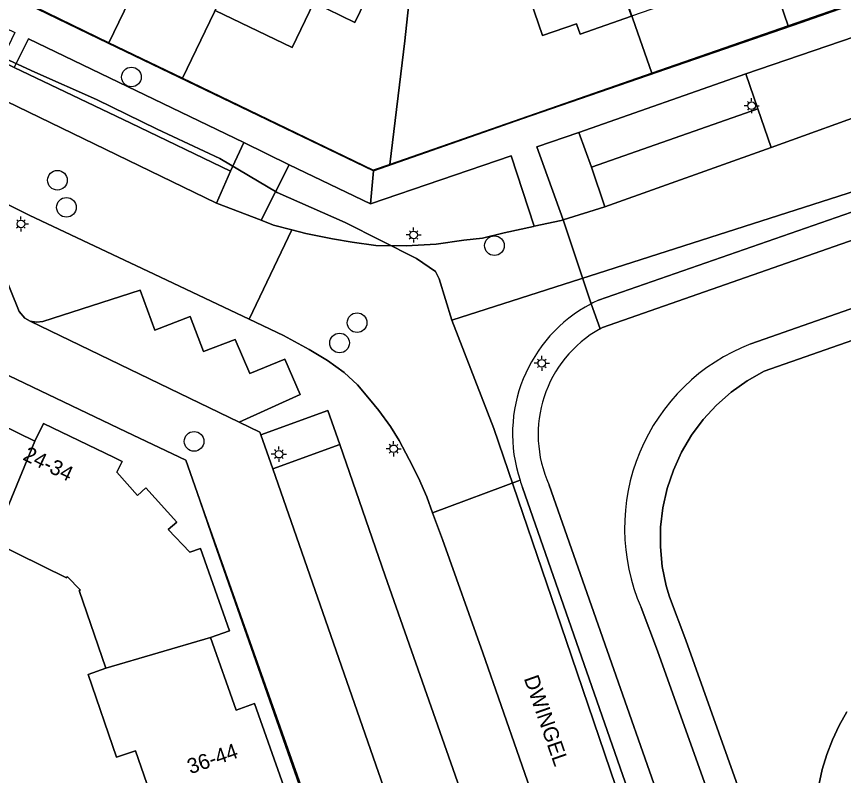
# Model space of a CAD drawing. Extents: x 124901 to 125496, y 515369 to 515789.
# Drawn here: x 125323.3 to 125378, y 515560.1 to 515610.2 of the extents above; entities that cross this region are included whole.
import ezdxf

# ---------------------------------------------------------------- set-up
doc = ezdxf.new("R2010")
doc.units = 0
for name, color, linetype in [('Berm', 7, 'Continuous'), ('Gebouw', 7, 'Continuous'), ('Inrit', 7, 'Continuous'), ('Lichtmast', 7, 'Continuous'), ('Onbegroeid terrein', 7, 'Continuous'), ('Parkeren', 7, 'Continuous'), ('Perceelsgrenzen', 7, 'Continuous'), ('Putten', 7, 'Continuous'), ('Scheiding', 7, 'Continuous'), ('Teksten', 7, 'Continuous'), ('Vegetatie', 7, 'Continuous'), ('Voetpad', 7, 'Continuous'), ('Water', 7, 'Continuous'), ('Wegen drempel verkeerseiland', 7, 'Continuous'), ('Wegen lokale weg', 7, 'Continuous')]:
    doc.layers.add(name, color=color, linetype=linetype)

msp = doc.modelspace()

# ---------------------------------------------------------------- linework, layer by layer
at = {"layer": 'Berm'}
for points in [[(125410.926, 515602.835), (125410.786, 515604.876), (125410.291, 515606.52), (125362.019, 515589.66), (125361.874, 515589.581)], [(125371.825, 515588.577), (125407.43, 515601.037), (125410.404, 515597.859), (125410.926, 515602.835)], [(125358.506, 515579.257), (125369.841, 515546.911)], [(125370.167, 515525.912), (125361.577, 515507.943), (125364.809, 515506.424), (125365.599, 515506.052), (125368.756, 515512.727), (125374.572, 515524.721), (125376.357, 515528.013), (125376.824, 515529.274), (125377.068, 515530.536), (125377.185, 515532.051), (125377.232, 515533.336), (125377.157, 515534.454), (125377.004, 515535.615), (125376.571, 515537.55), (125374.806, 515542.701), (125371.741, 515551.276), (125365.658, 515568.312), (125364.58, 515571.173)]]:
    msp.add_lwpolyline(points, dxfattribs=at)
for centre, radius, start, end in [((125365.776, 515582.597), 8, 119.1891, 204.6751), ((125376.535, 515576.406), 13.05, 111.1555, 203.6422)]:
    msp.add_arc(centre, radius, start, end, dxfattribs=at)
at = {"layer": 'Gebouw'}
for points in [[(125341.51, 515608.16), (125342.95, 515611.13), (125345.67, 515609.82), (125348.53, 515615.73), (125345.576, 515617.156), (125345.15, 515616.273), (125343.214, 515617.208), (125344.956, 515620.809), (125344.931, 515620.821), (125342.181, 515622.149), (125342.036, 515622.219), (125336.431, 515610.613)], [(125351.455, 515619.162), (125353.465, 515613.432), (125356.192, 515614.378), (125356.733, 515612.819), (125358.075, 515608.952), (125360.315, 515609.732), (125360.555, 515609.042), (125363.95, 515610.227), (125360.703, 515619.532), (125357.783, 515618.514), (125356.895, 515621.064)], [(125316.47, 515578.03), (125315.95, 515576.86), (125321.2, 515574.34), (125321.76, 515575.5), (125324.52, 515582.16), (125319.95, 515584.37), (125320.51, 515585.54), (125315.398, 515588.013), (125315.28, 515588.07), (125311.57, 515580.39)], [(125333.89, 515576.81), (125331.84, 515579.07), (125331.29, 515578.56), (125329.93, 515580.1), (125330.28, 515580.82), (125329.75, 515581.076), (125325.08, 515583.33), (125324.52, 515582.16), (125321.76, 515575.5), (125326.6, 515573.13), (125326.65, 515573.22), (125327.54, 515572.32), (125327.44, 515572.29), (125329.21, 515567.16), (125336.13, 515569.19), (125337.37, 515569.62), (125335.46, 515575.07), (125334.75, 515574.83), (125333.33, 515576.31)], [(125331.6, 515556.44), (125333.5, 515550.97), (125334.74, 515551.4), (125341.4, 515554.1), (125339.73, 515558.89), (125340.96, 515559.33), (125339.04, 515564.82), (125337.81, 515564.39), (125336.13, 515569.19), (125329.21, 515567.16), (125328.03, 515566.73), (125329.91, 515561.27), (125331.16, 515561.69), (125332.84, 515556.88)]]:
    msp.add_lwpolyline(points, close=True, dxfattribs=at)
at = {"layer": 'Inrit'}
for points in [[(125378.669, 515608.861), (125371.508, 515606.42), (125372.3, 515604.105), (125373.169, 515601.564), (125380.382, 515604.143), (125379.481, 515606.624)], [(125362.177, 515597.633), (125361.312, 515600.252), (125360.459, 515602.535), (125357.695, 515601.597), (125359.425, 515596.766)], [(125339.465, 515596.749), (125341.317, 515600.419), (125338.322, 515601.888), (125337.438, 515599.997), (125336.519, 515597.882)]]:
    msp.add_lwpolyline(points, close=True, dxfattribs=at)
at = {"layer": 'Lichtmast'}
for p, q in [((125371.674, 515604.525), (125371.604, 515604.596)), ((125371.886, 515604.613), (125371.886, 515604.813)), ((125372.098, 515604.525), (125372.169, 515604.597)), ((125371.586, 515604.314), (125371.386, 515604.313)), ((125371.674, 515604.101), (125371.602, 515604.03)), ((125371.886, 515604.013), (125371.886, 515603.813)), ((125372.098, 515604.101), (125372.168, 515604.03)), ((125372.186, 515604.313), (125372.386, 515604.313)), ((125323.596, 515596.801), (125323.596, 515597.001)), ((125323.384, 515596.713), (125323.314, 515596.784)), ((125323.808, 515596.713), (125323.879, 515596.785)), ((125323.896, 515596.501), (125324.096, 515596.501)), ((125323.384, 515596.289), (125323.312, 515596.218)), ((125323.596, 515596.201), (125323.596, 515596.001)), ((125323.808, 515596.289), (125323.878, 515596.218)), ((125349.247, 515595.775), (125349.047, 515595.774)), ((125349.335, 515595.986), (125349.265, 515596.057)), ((125349.547, 515596.074), (125349.547, 515596.274)), ((125349.759, 515595.986), (125349.83, 515596.058)), ((125349.847, 515595.774), (125350.047, 515595.774)), ((125349.335, 515595.562), (125349.263, 515595.491)), ((125349.547, 515595.474), (125349.547, 515595.274)), ((125349.759, 515595.562), (125349.829, 515595.491)), ((125357.805, 515587.509), (125357.735, 515587.58)), ((125358.017, 515587.597), (125358.017, 515587.797)), ((125358.229, 515587.509), (125358.3, 515587.581)), ((125357.717, 515587.298), (125357.517, 515587.297)), ((125357.805, 515587.085), (125357.733, 515587.014)), ((125358.229, 515587.085), (125358.299, 515587.014)), ((125358.317, 515587.297), (125358.517, 515587.297)), ((125358.017, 515586.997), (125358.017, 515586.797)), ((125348.223, 515581.95), (125348.223, 515582.15)), ((125340.431, 515581.505), (125340.361, 515581.576)), ((125340.643, 515581.593), (125340.643, 515581.793)), ((125340.855, 515581.505), (125340.926, 515581.577)), ((125347.923, 515581.651), (125347.723, 515581.65)), ((125348.011, 515581.862), (125347.941, 515581.933)), ((125348.435, 515581.862), (125348.506, 515581.934)), ((125348.523, 515581.65), (125348.723, 515581.65)), ((125340.343, 515581.294), (125340.143, 515581.293)), ((125340.431, 515581.081), (125340.359, 515581.01)), ((125340.855, 515581.081), (125340.925, 515581.01)), ((125340.943, 515581.293), (125341.143, 515581.293)), ((125348.011, 515581.438), (125347.939, 515581.367)), ((125348.223, 515581.35), (125348.223, 515581.15)), ((125348.435, 515581.438), (125348.505, 515581.367)), ((125340.643, 515580.993), (125340.643, 515580.793))]:
    msp.add_line(p, q, dxfattribs=at)
for centre in [(125371.886, 515604.313), (125323.596, 515596.501), (125349.547, 515595.774), (125358.017, 515587.297), (125348.223, 515581.65), (125340.643, 515581.293)]:
    msp.add_circle(centre, 0.25, dxfattribs=at)
at = {"layer": 'Onbegroeid terrein'}
msp.add_lwpolyline([(125353.465, 515613.432), (125351.455, 515619.162), (125356.895, 515621.064), (125357.783, 515618.514), (125360.703, 515619.532), (125360.14, 515621.146), (125362.915, 515622.113), (125362.59, 515623.046), (125368.161, 515624.989), (125370.174, 515619.255), (125367.444, 515618.296), (125367.991, 515616.739), (125369.345, 515612.882), (125367.109, 515612.102), (125367.349, 515611.413), (125363.95, 515610.227), (125360.555, 515609.042), (125360.315, 515609.732), (125358.075, 515608.952), (125356.733, 515612.819), (125356.192, 515614.378)], close=True, dxfattribs=at)
for points in [[(125306.97, 515619.275), (125328.714, 515608.752), (125346.892, 515600.023), (125356.759, 515603.471), (125375.169, 515609.812), (125392.301, 515615.845)], [(125348.53, 515615.73), (125345.67, 515609.82), (125342.95, 515611.13), (125341.51, 515608.16), (125336.431, 515610.613)], [(125342.972, 515556.928), (125335.865, 515576.993), (125334.482, 515580.899), (125330.544, 515582.774), (125318.137, 515588.683)], [(125319.95, 515584.37), (125324.52, 515582.16), (125325.08, 515583.33), (125329.75, 515581.076), (125330.28, 515580.82), (125329.93, 515580.1), (125331.29, 515578.56), (125331.84, 515579.07), (125333.89, 515576.81), (125333.33, 515576.31), (125334.75, 515574.83), (125335.46, 515575.07), (125337.37, 515569.62), (125336.13, 515569.19), (125337.81, 515564.39), (125339.04, 515564.82), (125340.96, 515559.33)], [(125332.84, 515556.88), (125331.16, 515561.69), (125329.91, 515561.27), (125328.03, 515566.73), (125329.21, 515567.16), (125327.44, 515572.29), (125327.54, 515572.32), (125326.65, 515573.22), (125326.6, 515573.13), (125321.76, 515575.5)]]:
    msp.add_lwpolyline(points, dxfattribs=at)
at = {"layer": 'Parkeren'}
for points in [[(125336.519, 515597.882), (125337.438, 515599.997), (125330.856, 515603.155), (125323.154, 515606.845), (125322.28, 515607.264), (125317.991, 515609.319), (125316.985, 515609.801), (125315.999, 515607.807)], [(125361.312, 515600.252), (125362.177, 515597.633), (125373.169, 515601.564), (125372.3, 515604.105)], [(125338.012, 515583.417), (125342.054, 515585.227), (125341.043, 515587.567), (125338.714, 515586.619), (125337.747, 515588.874), (125335.651, 515588.079), (125334.772, 515590.382), (125332.44, 515589.485), (125331.466, 515592.126), (125325.041, 515590.061), (125324.618, 515590.025), (125324.203, 515590.081)], [(125348.263, 515557.283), (125352.745, 515558.815), (125352.736, 515558.839), (125347.675, 515573.262), (125344.68, 515581.93), (125340.233, 515580.319)]]:
    msp.add_lwpolyline(points, close=True, dxfattribs=at)
at = {"layer": 'Perceelsgrenzen'}
for points in [[(125374.301, 515609.602), (125365.21, 515636.12), (125368.75, 515637.34), (125374.35, 515639.28), (125378.923, 515625.863), (125383.515, 515612.815)], [(125365.292, 515606.46), (125360.724, 515619.519), (125356.08, 515632.98), (125365.21, 515636.12), (125374.301, 515609.602)], [(125329.408, 515608.477), (125324.548, 515610.824), (125330.57, 515623.313), (125336.513, 515635.621), (125336.653, 515635.553), (125341.375, 515633.273), (125335.859, 515621.848), (125335.643, 515621.952), (125335.217, 515621.069), (125335.433, 515620.965)], [(125334.269, 515606.129), (125329.408, 515608.477), (125335.433, 515620.965), (125335.217, 515621.069), (125335.643, 515621.952), (125335.859, 515621.848), (125341.375, 515633.273), (125346.08, 515631), (125346.238, 515630.925), (125340.722, 515619.499), (125340.938, 515619.395), (125340.512, 515618.512), (125340.296, 515618.617)], [(125347.97, 515600.42), (125348.96, 515608.6), (125351.11, 515628.61), (125352.36, 515631.64), (125356.08, 515632.98), (125360.724, 515619.519), (125365.292, 515606.46)], [(125334.269, 515606.129), (125340.296, 515618.617), (125340.512, 515618.512), (125340.938, 515619.395), (125340.722, 515619.499), (125346.238, 515630.925), (125351.11, 515628.61), (125348.96, 515608.6), (125347.97, 515600.42), (125346.87, 515600.05)]]:
    msp.add_lwpolyline(points, close=True, dxfattribs=at)
for points in [[(125316.445, 515610.498), (125321.38, 515607.963), (125324.515, 515606.531), (125328.594, 515604.73), (125332.608, 515602.764), (125336.73, 515600.825), (125340.526, 515598.575), (125345.025, 515596.601), (125349.739, 515594.219), (125350.982, 515593.372), (125351.229, 515592.881), (125352.068, 515590.151), (125423.088, 515612.915)], [(125383.515, 515612.815), (125374.301, 515609.602), (125365.292, 515606.46), (125347.97, 515600.42), (125346.87, 515600.05), (125334.269, 515606.129), (125329.408, 515608.477), (125324.548, 515610.824)], [(125423.088, 515612.915), (125352.068, 515590.151), (125354.844, 515582.98), (125359.632, 515568.992), (125367.282, 515546.531), (125373.39, 515529.447), (125374.833, 515525.657), (125370.2, 515515.457), (125361.451, 515496.989), (125354.147, 515481.936), (125345.37, 515463.116), (125339.28, 515450.017), (125332.914, 515437.391), (125330.261, 515431.98), (125328.194, 515427.596), (125330.281, 515426.402), (125332.521, 515425.055), (125348.134, 515457.345), (125358.716, 515479.229), (125369.827, 515502.206), (125375.06, 515499.729), (125385.193, 515494.823)], [(125339.28, 515450.017), (125345.37, 515463.116), (125354.147, 515481.936), (125361.451, 515496.989), (125370.2, 515515.457), (125374.833, 515525.657), (125373.39, 515529.447), (125367.282, 515546.531), (125359.632, 515568.992), (125354.844, 515582.98), (125352.068, 515590.151), (125351.229, 515592.881), (125350.982, 515593.372), (125349.739, 515594.219), (125345.025, 515596.601), (125340.526, 515598.575), (125336.73, 515600.825), (125332.608, 515602.764), (125328.594, 515604.73), (125324.515, 515606.531), (125321.38, 515607.963), (125316.445, 515610.498)], [(125271.62, 515558.71), (125280.85, 515577.9), (125284.46, 515579.06), (125285.19, 515580.58), (125290.142, 515590.841), (125293.8, 515598.46), (125295.97, 515602.96), (125301.013, 515600.518), (125305.831, 515598.186), (125316.893, 515592.83), (125318.137, 515588.683), (125334.482, 515580.899), (125336.39, 515575.4), (125352.406, 515529.691)], [(125271.62, 515558.71), (125280.85, 515577.9), (125284.46, 515579.06), (125285.19, 515580.58), (125290.175, 515578.191), (125292.62, 515577.02), (125295.08, 515575.85), (125296.14, 515578.13), (125299.998, 515586.108), (125305.831, 515598.186), (125316.893, 515592.83), (125318.137, 515588.683), (125334.482, 515580.899), (125336.39, 515575.4), (125352.406, 515529.691)], [(125378.185, 515564.28), (125377.676, 515563.369), (125377.233, 515562.425), (125376.859, 515561.451), (125376.554, 515560.454), (125376.322, 515559.437), (125376.162, 515558.406), (125376.077, 515557.386), (125376.061, 515556.363), (125376.114, 515555.341), (125376.237, 515554.325), (125376.428, 515553.32), (125376.687, 515552.33), (125377.013, 515551.36), (125377.404, 515550.414), (125377.858, 515549.497), (125378.373, 515548.613)], [(125378.373, 515548.613), (125377.858, 515549.497), (125377.404, 515550.414), (125377.013, 515551.36), (125376.687, 515552.33), (125376.428, 515553.32), (125376.237, 515554.325), (125376.114, 515555.341), (125376.061, 515556.363), (125376.077, 515557.386), (125376.162, 515558.406), (125376.322, 515559.437), (125376.554, 515560.454), (125376.859, 515561.451), (125377.233, 515562.425), (125377.676, 515563.369), (125378.185, 515564.28)]]:
    msp.add_lwpolyline(points, dxfattribs=at)
at = {"layer": 'Putten'}
for centre in [(125330.9, 515606.21), (125326.01, 515599.39), (125326.6, 515597.6), (125354.89, 515595.07), (125345.81, 515589.98), (125344.65, 515588.64), (125335.04, 515582.14)]:
    msp.add_circle(centre, 0.65, dxfattribs=at)
at = {"layer": 'Scheiding'}
for points in [[(125406.86, 515598.719), (125372.716, 515586.786)], [(125372.716, 515586.786), (125371.587, 515586.149), (125370.531, 515585.397), (125369.559, 515584.539), (125368.683, 515583.584), (125367.911, 515582.542), (125367.252, 515581.426), (125366.713, 515580.246), (125366.301, 515579.017), (125366.019, 515577.752), (125365.871, 515576.464), (125365.859, 515575.168), (125365.982, 515573.877), (125366.239, 515572.607), (125366.451, 515571.879)], [(125367.41, 515505.2), (125370.56, 515511.863), (125376.33, 515523.768), (125378.183, 515527.185), (125378.756, 515528.733), (125379.053, 515530.268), (125379.182, 515531.938), (125379.234, 515533.366), (125379.148, 515534.652), (125378.975, 515535.965), (125378.499, 515538.094), (125376.694, 515543.362), (125373.624, 515551.949), (125367.536, 515569.001), (125366.451, 515571.879)]]:
    msp.add_lwpolyline(points, dxfattribs=at)
at = {"layer": 'Vegetatie'}
for points in [[(125338.322, 515601.888), (125324.098, 515608.743), (125323.154, 515606.845), (125330.856, 515603.155), (125337.438, 515599.997)], [(125360.459, 515602.535), (125361.312, 515600.252), (125372.3, 515604.105), (125371.508, 515606.42)], [(125347.051, 515595.077), (125349.051, 515595.065), (125351.047, 515595.161), (125352.855, 515595.425), (125354.095, 515595.561), (125355.524, 515595.921), (125357.463, 515596.339), (125357.522, 515596.351), (125355.984, 515601.012), (125346.692, 515597.835), (125341.317, 515600.419), (125339.465, 515596.749), (125340.291, 515596.43), (125341.491, 515596.112), (125342.424, 515595.865), (125344.179, 515595.511), (125345.489, 515595.297)]]:
    msp.add_lwpolyline(points, close=True, dxfattribs=at)
for points in [[(125358.958, 515554.253), (125354.126, 515568.16), (125351.451, 515575.663), (125350.799, 515577.428), (125350.415, 515578.466), (125349.873, 515579.739), (125349.261, 515580.944), (125348.59, 515582.203), (125348.008, 515583.113), (125347.257, 515584.185), (125346.641, 515584.934), (125345.844, 515585.871), (125344.946, 515586.681), (125343.845, 515587.49), (125342.652, 515588.211), (125340.942, 515589.144), (125338.677, 515590.212), (125332.396, 515593.175), (125324.142, 515597.092), (125322.01, 515598.138)], [(125320.995, 515596.842), (125323.481, 515590.712), (125323.845, 515590.28), (125324.203, 515590.081), (125324.618, 515590.025), (125325.041, 515590.061), (125331.466, 515592.126), (125332.44, 515589.485), (125334.772, 515590.382), (125335.651, 515588.079), (125337.747, 515588.874), (125338.714, 515586.619), (125341.043, 515587.567), (125342.054, 515585.227), (125338.012, 515583.417), (125339.384, 515582.755), (125339.449, 515582.57), (125343.888, 515584.176), (125344.68, 515581.93), (125347.675, 515573.262), (125352.736, 515558.839)]]:
    msp.add_lwpolyline(points, dxfattribs=at)
at = {"layer": 'Voetpad'}
for points in [[(125308.913, 515616.039), (125323.183, 515609.153), (125322.28, 515607.264), (125323.154, 515606.845), (125324.098, 515608.743), (125338.322, 515601.888), (125341.317, 515600.419), (125346.692, 515597.835), (125346.892, 515600.023), (125328.714, 515608.752), (125306.97, 515619.275)], [(125392.301, 515615.845), (125375.169, 515609.812), (125356.759, 515603.471), (125346.892, 515600.023), (125346.692, 515597.835), (125355.984, 515601.012), (125357.522, 515596.351), (125359.301, 515596.727), (125359.425, 515596.766), (125357.695, 515601.597), (125360.459, 515602.535), (125371.508, 515606.42), (125378.669, 515608.861), (125389.667, 515612.721)], [(125410.908, 515608.56), (125361.761, 515591.467)], [(125361.28, 515591.231), (125361.874, 515589.581), (125362.019, 515589.66), (125410.291, 515606.52), (125411.895, 515607.08)], [(125361.874, 515589.581), (125361.28, 515591.231)], [(125356.75, 515579.092), (125368.118, 515546.485)], [(125369.841, 515546.911), (125358.506, 515579.257)]]:
    msp.add_lwpolyline(points, dxfattribs=at)
msp.add_lwpolyline([(125343.888, 515584.176), (125339.449, 515582.57), (125340.233, 515580.319), (125344.68, 515581.93)], close=True, dxfattribs=at)
for centre, radius, start, end in [((125366.232, 515581.746), 10.7, 114.7, 117.5693), ((125365.809, 515582.626), 9.724, 117.7604, 198.3407), ((125365.776, 515582.597), 8, 119.1891, 204.6751), ((125365.731, 515582.6), 9.642, 198.34, 201.3347)]:
    msp.add_arc(centre, radius, start, end, dxfattribs=at)
at = {"layer": 'Water'}
for points in [[(125391.956, 515564.185), (125398.205, 515563.214), (125410.404, 515597.859), (125407.43, 515601.037), (125371.825, 515588.577)], [(125406.86, 515598.719), (125372.716, 515586.786), (125371.587, 515586.149), (125370.531, 515585.397), (125369.56, 515584.538), (125368.683, 515583.584), (125367.911, 515582.542), (125367.252, 515581.426), (125366.713, 515580.247), (125366.301, 515579.017), (125366.019, 515577.752), (125365.871, 515576.464), (125365.859, 515575.168), (125365.982, 515573.877), (125366.24, 515572.607), (125366.451, 515571.879), (125367.536, 515569.001), (125373.624, 515551.949), (125376.694, 515543.362), (125378.499, 515538.094)], [(125378.499, 515538.094), (125376.694, 515543.362), (125373.624, 515551.949), (125367.536, 515569.001), (125366.451, 515571.879), (125366.24, 515572.607), (125365.982, 515573.877), (125365.859, 515575.168), (125365.871, 515576.464), (125366.019, 515577.752), (125366.301, 515579.017), (125366.713, 515580.247), (125367.252, 515581.426), (125367.911, 515582.542), (125368.683, 515583.584), (125369.56, 515584.538), (125370.531, 515585.397), (125371.587, 515586.149), (125372.716, 515586.786), (125406.86, 515598.719)], [(125364.58, 515571.173), (125365.658, 515568.312), (125371.741, 515551.276), (125374.806, 515542.701), (125376.571, 515537.55), (125377.004, 515535.615), (125377.157, 515534.454), (125377.232, 515533.336), (125377.185, 515532.051), (125377.068, 515530.536), (125376.824, 515529.274), (125376.357, 515528.013), (125374.572, 515524.721), (125368.756, 515512.727), (125365.599, 515506.052), (125364.886, 515504.544), (125363.142, 515500.855), (125362.738, 515500), (125357.851, 515489.665), (125346.912, 515466.932), (125337.01, 515446.725), (125327.894, 515428.026)]]:
    msp.add_lwpolyline(points, dxfattribs=at)
msp.add_arc((125376.535, 515576.406), 13.05, 111.1555, 203.6422, dxfattribs=at)
at = {"layer": 'Wegen drempel verkeerseiland'}
for points in [[(125361.28, 515591.231), (125359.425, 515596.766), (125359.301, 515596.727), (125357.522, 515596.351), (125357.463, 515596.339), (125355.524, 515595.921), (125354.095, 515595.561), (125352.855, 515595.425), (125351.047, 515595.161), (125349.051, 515595.065)], [(125349.051, 515595.065), (125347.051, 515595.077), (125345.489, 515595.297), (125344.179, 515595.511), (125342.424, 515595.865), (125341.491, 515596.112), (125338.677, 515590.212), (125340.942, 515589.144), (125342.652, 515588.211), (125343.845, 515587.49), (125344.946, 515586.681), (125345.844, 515585.871), (125346.641, 515584.934), (125347.257, 515584.185), (125348.008, 515583.113), (125348.59, 515582.203), (125349.261, 515580.944), (125349.873, 515579.739), (125350.415, 515578.466), (125350.799, 515577.428), (125356.579, 515579.566)]]:
    msp.add_lwpolyline(points, dxfattribs=at)
msp.add_arc((125365.809, 515582.626), 9.724, 117.7604, 198.3407, dxfattribs=at)
at = {"layer": 'Wegen lokale weg'}
for points in [[(125416.988, 515615.988), (125416.656, 515615.975), (125413.775, 515615.518), (125409.531, 515614.567), (125398.324, 515610.559), (125391.211, 515608.016), (125380.382, 515604.143), (125373.169, 515601.564), (125362.177, 515597.633), (125359.425, 515596.766), (125361.28, 515591.231)], [(125290.73, 515613.306), (125298.023, 515609.767), (125299.229, 515609.17), (125310.904, 515603.606), (125312.857, 515602.604), (125322.01, 515598.138), (125324.142, 515597.092), (125332.396, 515593.175), (125338.677, 515590.212), (125341.491, 515596.112), (125340.291, 515596.43), (125339.465, 515596.749), (125336.519, 515597.882), (125315.999, 515607.807), (125307.775, 515611.76)], [(125361.761, 515591.467), (125410.908, 515608.56)], [(125348.263, 515557.283), (125340.233, 515580.319), (125339.449, 515582.57), (125339.384, 515582.755), (125338.012, 515583.417), (125324.203, 515590.081), (125323.845, 515590.28), (125323.481, 515590.712), (125320.995, 515596.842)], [(125318.137, 515588.683), (125330.544, 515582.774), (125334.482, 515580.899), (125335.865, 515576.993), (125342.972, 515556.928)], [(125356.579, 515579.566), (125350.799, 515577.428), (125351.451, 515575.663), (125354.126, 515568.16), (125358.958, 515554.253), (125362.623, 515543.742), (125363.531, 515540.594), (125363.868, 515539.006), (125364.039, 515537.374), (125364.166, 515535.889), (125364.101, 515534.784), (125364.053, 515533.979), (125363.833, 515532.18), (125363.532, 515530.771), (125362.83, 515528.771), (125362.207, 515527.293), (125361.024, 515524.759), (125357.343, 515517.197), (125354.591, 515511.495), (125353.971, 515510.211)], [(125368.118, 515546.485), (125356.75, 515579.092)]]:
    msp.add_lwpolyline(points, dxfattribs=at)
for centre, radius, start, end in [((125366.232, 515581.746), 10.7, 114.7, 117.5693), ((125365.731, 515582.6), 9.642, 198.34, 201.3347)]:
    msp.add_arc(centre, radius, start, end, dxfattribs=at)

# ---------------------------------------------------------------- texts
at = {"layer": 'Teksten'}
for s, rotation, p in [('24-34', 334.2, (125323.658, 515580.952)), ('DWINGEL', 289.3, (125356.819, 515566.485)), ('36-44', 19.3, (125334.794, 515560.144))]:
    msp.add_text(s, height=1, rotation=rotation, dxfattribs=at).set_placement(p)

doc.saveas('drawing.dxf')
